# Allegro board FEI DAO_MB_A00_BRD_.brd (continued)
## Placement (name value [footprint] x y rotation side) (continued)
T56  -  [TPC12]  166.92 22.3 0 top
T57  -  [TPC12]  164.44 25.07 0 top
T58  -  [TPC12]  169.8 23.26 0 top
T59  -  [TPC12]  168.01 18.92 0 top
T60  -  [TPC12]  168.28 20.29 0 top
T61  -  [TPC12]  167.63 23.99 0 top
T62  -  [TPC12]  167.62 26.98 0 top
T63  -  [TPC12]  154.54 24.46 0 top
T104  -  [TPC12]  164.25 23.1 0 top
T107  -  [TPC12]  131.98 68.78 180 bottom
T108  -  [TPC12]  132.64 70.19 180 bottom
T109  -  [TPC12]  131.09 70.22 180 bottom
T110  -  [TPC12]  126.5 56.96 0 top
T117  -  [TPC12]  270.99 69.87 0 top
T118  -  [TPC12]  130.97 32.53 180 bottom
T119  -  [TPC12]  134.64 68.81 180 bottom
T120  -  [TPC12]  133.28 68.79 180 bottom
T121  -  [TPC12]  129.82 30.9 180 bottom
T122  -  [TPC12]  109.85 69.07 180 bottom
T123  -  [TPC12]  103.28 36.74 180 bottom
T124  -  [TPC12]  103.28 34.62 180 bottom
T125  -  [TPC12]  260.05 85 0 top
T126  -  [TPC12]  259.19 89.44 0 top
T127  -  [TPC12]  130.7 68.79 180 bottom
T128  -  [TPC12]  129.7 59.55 0 top
T130  -  [TPC12]  270.24 83.14 0 top
T131  -  [TPC12]  271.3 81.32 0 top
T132  -  [TPC12]  105.5 66.51 180 bottom
T133  -  [TPC12]  265.14 82.15 0 top
T139  -  [TPC12]  259.97 65.78 0 top
T140  -  [TPC12]  262.06 87.4 0 top
T141  -  [TPC12]  261.42 64.13 0 top
T142  -  [TPC12]  285.64 88.64 0 top
T143  -  [TPC12]  283.23 88.61 0 top
T144  -  [TPC12]  10.6 69.97 0 top
T145  -  [TPC12]  252.9 72.55 0 top
T148  -  [TPC12]  257.26 75.96 0 top
T151  -  [TPC12]  263.02 64.7 0 top
T154  -  [TPC12]  257.31 74.58 0 top
T155  -  [TPC12]  255.68 69.56 0 top
T156  -  [TPC12]  257.04 69.59 0 top
T157  -  [TPC12]  260.41 86.75 0 top
T158  -  [TPC12]  262.04 85.24 0 top
T159  -  [TPC12]  276.22 80.87 0 top
T160  -  [TPC12]  273.06 81.29 0 top
T161  -  [TPC12]  274.88 82.13 0 top
T162  -  [TPC12]  272.17 75.68 0 top
T163  -  [TPC12]  269.19 85.07 0 top
T164  -  [TPC12]  271.18 84.91 0 top
T165  -  [TPC12]  289.68 65.11 0 top
T167  -  [TPC12]  284.38 70.89 0 top
T168  -  [TPC12]  283.32 72.3 0 top
T169  -  [TPC12]  295.1 64.82 0 top
T170  -  [TPC12]  278.02 67.28 0 top
T171  -  [TPC12]  296.59 49.49 0 top
T172  -  [TPC12]  294.85 50.61 0 top
T173  -  [TPC12]  272.79 64.37 0 top
T174  -  [TPC12]  272.7 62.38 0 top
T175  -  [TPC12]  274.03 60.73 0 top
T176  -  [TPC12]  288.51 51.2 0 top
T177  -  [TPC12]  293.52 51.15 0 top
T178  -  [TPC12]  276.57 57.55 0 top
T183  -  [TPC12]  289.46 51.6 0 top
T184  -  [TPC12]  34.4 32.22 0 top
T185  -  [TPC12]  296.92 64.16 0 top
T186  -  [TPC12]  25.58 41.88 0 top
TR1  -  [TAIMA_IH-115-F_24P]  304.36 72.2 90 bottom
U1  -  [IVY-BRIDGE_BGA_1023P]  131.79 36.09 90 bottom
U2  -  [SLG55584AVTR_TDFN8_2X2]  306.49 62.79 270 bottom
U4  -  [RT9818A-44GU3_SC70-3]  189.4 31.08 180 bottom
U7  -  [TC7SH08FU_SSOP5]  187.25 28.01 270 bottom
U9  -  [EMC4021-1-EZK-TR_QFN32_5X5]  157.69 105.47 0 bottom
U15  -  [TC7SH08FU_SSOP5]  292.12 88.21 270 top
U31  -  [82579_QFN48_6X6]  284.71 78.55 0 top
U37  -  [SSX44-B-D-T1_TSSOP28]  260.11 46.98 90 bottom
U38  -  [OZ600FJ0LN_QFN32_5X5]  278.38 15.6 270 top
U39  -  [AT97SC3204-X2A14-AB_TSSOP28]  260.9 46.98 90 bottom
U40  -  [SRV05-4PTCT_SOT23-6]  288.25 29.27 90 bottom
U44  -  [PS8513BTQFN20GTR-A0_TQFN20_4X4]  238.55 75.18 0 top
U46  -  [ECE5048-LZY_DQFN132_11X11]  260.34 69.86 0 top
U48  -  [G547I2P81U_MSOP8]  18.72 43.19 0 top
U50  -  [TC7SH08FU_SSOP5]  138.41 21.93 180 bottom
U51  -  [MEC5055-LZY_DQFN132_11X11]  293.46 54.6 90 top
U52  -  [W25Q64CVSSIG_SO8]  211.78 28.82 180 bottom
U53  -  [W25Q32BVSSIG_SO8]  208 23.13 0 bottom
U58  -  [TC7SH08FU_SSOP5]  258.68 88.29 180 top
U72  -  [92HD90B2X5NLGXZBX8_QFN48_7X7]  34.86 34.66 90 top
U73  -  [74AHCT1G125GW_SOT353-5]  19.13 78.65 270 top
U74  -  [74AHCT1G125GW_SOT353-5]  16.42 77.35 90 top
U75  -  [TPS2560DRCR-PG1P1_SON10_3X3]  306.56 50.88 90 bottom
U76  -  [AP2330W-7_SC59-3]  81.9 95.86 90 bottom
U77  -  [AP2330W-7_SC59-3]  10.08 61.85 180 bottom
UC1  -  [SN74LVC1G07DCKR_SC70-5]  137.21 71.32 90 bottom
UC2  -  [74AHC1G09GW_TSSOP5]  105.72 83.61 0 bottom
UH3  -  [TC7SH08FU_SSOP5]  181.33 18.09 0 bottom
UH4  -  [BD82PPSM-QNHN-A0_BGA_989P]  170.53 18.65 270 bottom
UH5  -  [TC7SH08FU_SSOP5]  180.46 11.25 270 bottom
Y3  -  [Y_X3G025000DI1H-H_4P]  295.51 76.23 90 top
Y6  -  [Y_Q13FC1350000_2P]  290.21 47.75 0 top
YH1  -  [Y_Q13FC1350000_2P]  178.95 29.19 270 bottom
YH2  -  [Y_Q22FA2380049900_4P]  161.48 50.44 0 bottom

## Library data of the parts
C36-C39 C1169 = C_0603NEW: room: LOM
C44 C45 C550-C554 CE3 CE4 = C_0402NEW: room: TPM
C219 = C_0805NEW: room: FAN
C243 C292 C293 C297-C299 C301 C302 R159 = C_0402NEW: room: LVDS
C246 C296 C300 = C_0603NEW: room: LVDS
C266 C270-C274 C277 C278 C282 C723 C725-C729 C731 C732 C739 C1179 = C_0402NEW: room: THERMAL
C288 C289 C756 C758 PC5 PC76 PC77 PC83 PC86 PC90 PC91 PC100 PC102 PC104 PC105 PC108 PC109 PC112 PC113 PC116 PC255 PC275 PC277-PC279 PC281 PC282 PC301 PC304 PC305 PC401 PC402 PC404 PC405 PC407 PC408 PC501 PC502 PC504 PC506 PC508 PC510 PC742 PC744 PC750 PC1304 PC1312 PC1318 PC1334 PC1338 PC1339 = C_0402NEW: room: ETY-ROOM
C337 C346-C353 C1216-C1223 = C_0402NEW: room: HDMI
C338 = C_0805NEW: room: HDMI
C412 C413 C654 C675 C715 C1231 C1234 C1235 C1242-C1244 = C_0402NEW: room: USB
C458-C461 C463 C466-C471 C476-C478 = C_0402NEW: room: LAN
C462 C464 C475 = C_0603NEW: room: LAN
C559 C562 C563 C565 C567-C569 C571 C573-C576 C579 CE757 = C_0402NEW: room: OZ600
C560 C561 C564 C566 C572 C577 C578 = C_0603NEW: room: OZ600
C593 C594 C597 C599 C610-C612 C614 C644 = C_0402NEW: room: WWAN
C595 C596 C598 C600-C607 C632 = C_0402NEW: room: WLAN
C608 = C_0603NEW: room: WLAN
C609 C661-C666 C763 C765 C767 C774-C777 C779-C787 C967 C981-C983 C1246-C1249 C1278 C1279 C1316-C1333 CH53 CH111 CH112 PC78 PC1211-PC1217 = C_0402NEW
C613 = C_0805NEW: room: WWAN
C615 = C_D2E: room: WWAN
C616 C628-C631 = C_0402NEW: room: SIM
C617 C618 C1309 C1310 CH2-CH5 CH18 CH19 CH31-CH35 CH43 CH45-CH52 CH54-CH56 CH59 CH60 CH63 CH66-CH69 CH72 CH74-CH79 CH81 CH82 CH84 CH86-CH93 CH96-CH98 CH101-CH104 CH107 CH109 CH110 = C_0402NEW: room: PCH
C619-C625 C627 C650 = C_0402NEW: room: WPAN
C626 = C_0603NEW: room: WPAN
C651 C1245 = C_B2: room: USB
C676 C1230 = C_0805NEW: room: USB
C705 C714 = C_0603NEW: room: SIO
C706-C710 C712 C713 C716 = C_0402NEW: room: SIO
C720-C722 C735 C737 C741-C744 C747 = C_0402NEW: room: KBC
C730 = C_0603NEW: room: THERMAL
C740 = C_0603NEW: room: KBC
C745 C746 = C_0402NEW: room: FLASH ROM
C749-C752 C755 C759 = C_0402NEW: room: TOUCH.PAD
C760 C768 C769 C772 = C_0603NEW: room: +3.3V_LAN SOURCE
C761 = C_0805NEW: room: +5V_RUN_SOURCE
C762 = C_0402NEW: room: +3.3V_ALW_PCH SOURCE
C764 = C_0805NEW: room: +3.3V_RUN_SOURCE
C766 = C_0402NEW: room: +3.3V_RUN_SOURCE
C770 = C_0402NEW: room: +3.3VM SOURCE
C771 = C_0402NEW: room: +1.5V_RUN_SOURCE
C773 = C_0402NEW: room: +1.05VRUN_SOURCE
C778 = C_0402NEW: room: LVDS SW
C952 C954-C956 C958 C960 C962-C966 C1163 C1180 = C_0603NEW: room: CODEC
C953 C957 C959 C961 C973-C980 C994 C1105 C1106 = C_0402NEW: room: CODEC
C1104 = C_1808: room: LOM
C1167 C1168 = C_0402NEW: room: LOM
C1177 C1178 = C_0805NEW: room: LAN
C1201-C1210 C1224 C1225 = C_0402NEW: room: CRT
C1211-C1213 = C_0402NEW: room: AJACK
C1232 = C_B2: room: ESATA
C1233 C1236-C1239 = C_0402NEW: room: ESATA
C1304 = C_0402NEW: room: FP
C1305-C1307 = C_0402NEW: room: BT
C1308 = C_0402NEW: room: LID
C1311 = C_0402NEW: room: CAM
CC65 = C_0402NEW: room: XDP1
CC135 = C_0603NEW: room: +1.5V_CPU_VDDQ SOURCE
CC136 = C_0402NEW: room: +1.5V_CPU_VDDQ SOURCE
CC140 CC141 CC149 CC150 CC156 CC174 CC175 CC177-CC179 CC250-CC264 CC573 CC574 PC1137-PC1142 PC1147-PC1151 PC1172 PC1175-PC1186 PC1188-PC1210 = C_0402NEW: room: CPU
CC161-CC166 CC168-CC171 CC180 CC181 CC183 = C_0603NEW: room: CPU
CC167 PC1157 = C_D3: room: CPU
CC172 CC176 PC1158 = C_D2: room: CPU
CD1-CD8 CD17-CD30 CD39-CD44 = C_0402NEW: room: MEMORY
CD9-CD15 CD31-CD37 = C_0603NEW: room: MEMORY
CD16 CD38 = C_D3: room: MEMORY
CH1 CH6 = C_0402NEW: room: XDP2
CH30 CH44 CH70 CH71 CH73 CH85 CH106 = C_0603NEW: room: PCH
CH36 CH64 CH65 CH105 = C_0805NEW: room: PCH
CH94 CH95 = C_B2: room: PCH
CMOS1 ME1 = SHORTPADS: User Part Number: PART#; room: PCH
D2 D31 = RB751S40T1_SOD523-2: room: ETY-ROOM
D6 = BAT54CW_SOT323-3: room: LVDS
D9 D73 = PESD5V0U2BT_SOT23-3
D23 PD7 = PESD24VS2UT_SOT23-3
D37 = PESD5V0U2BT_SOT23-3: room: TOUCH.PAD
D59 D62 D65-D69 DH2 DH3 = RB751V40_SC76-2: room: ETY-ROOM
D72 D77 D83 D90 = PESD5V0U2BT_SOT23-3: room: USB
D78 = IP4292CZ10-TB_XSON10U10: room: ETY-ROOM
D81 D82 = AZ5125-02SPR7G_SOT23-3: room: ETY-ROOM
D87 = PESD5V0U2BT_SOT23-3: room: ESATA
D88 = IP4292CZ10-TB_XSON10U10: room: ESATA
D89 = IP4292CZ10-TB_XSON10U10: room: USB
D91-D94 = RB751S40T1_SOD523-2
DE1 DE2 = AZ5125-02SPR7G_SOT23-3: room: CAM
FD1-FD4 = FIDUCIAL_C40M80
H1-H3 H5 H7 H9 H10 = H_2P8
H4 H6 H8 H26 = H_2P3
H11 = H_5P4N
H12 = H_2P0
H13 H14 H16 H17 = H_3P2
H19-H22 = H_3P8
H23 = H_2P8X2P3
H24 = H_2P5X2P0
JBT1 = ACES_50224-0120N-001_12P: room: BT
JCAP2 JLED1 = ACES_50506-00841-P01_8P-T
JCRT1 = TYCO_2041127-1_15P: room: ETY-ROOM
JDEG2 = HB_A531015-SCHR21_10P: room: KBC
JDIMM1 = TYCO_2-2013022-1_204P: room: ETY-ROOM
JDIMM2 = TYCO_2-2013287-1_204P: room: ETY-ROOM
JESA1 = TAIWI_EU147-167CRL-TWD_16P: room: ESATA
JFAN1 = ACES_50271-0040N-001_4P: room: ETY-ROOM
JFP1 = ACES_50505-00641-001_6P-T: room: ETY-ROOM
JHDMI1 = HONGL_13-13201904CP_19P: room: HDMI
JHP1 = SINGA_2SJ3053-100111F_6P-T: room: ETY-ROOM
JLID1 = HB_A080415-SAHR21_4P-T: room: ETY-ROOM
JLOM1 = SANTA_130456-241_13P-T
JLVDS1 = STARC_107K40-000001-G2_40P: room: ETY-ROOM
JLVDS2 = E-T_3703K-F12N-03R_12P
JMINI1 = LCN_DAN08-52406-0500_52P: room: WWAN
JMINI2 JMINI3 = LCN_DAN08-52406-0500_52P: room: ETY-ROOM
JRTC1 = ACES_50271-0020N-001_2P: room: ETY-ROOM
JSC1 = HB_A081015-SAHR21_10P-T: room: ETY-ROOM
JSD1 = T-SOL_156-4000000606_15P-T: room: ETY-ROOM
JSIM1 = HB_5620821-SICR11_9P: room: ETY-ROOM
JSNIF1 = ACES_50504-0040N-001_4P: room: IO
JSPK1 = ACES_50269-00401-001_4P-T: room: ETY-ROOM
JTAA1 = ACES_50169-01441-001_14P-T: room: ETY-ROOM
JTAG1 = SHORTPADS: User Part Number: PART#; room: KBC
JTP1 = ACES_50506-01641-P01_16P-T: room: TOUCH.PAD
JUSB1 = SANTA_373070-1_9P-T: room: ETY-ROOM
JUSB3 = SANTA_373070-1_9P-T: room: USB
JXDP1 = MOLEX_52435-2671_26P-T: room: ETY-ROOM
JXDP2 = MOLEX_52435-2671_26P-T: room: PCH
L10 = MURAT_DLW21SN121SQ2L_4P: room: LVDS
L19-L22 = MURAT_DLW21SN900HQ2L_0805_4P-S: room: HDMI
L29 = TAIYO_CBC2012T4R7M_2P: room: LAN
L44 L47 = MURAT_BLM18BD601SN1D_2P: room: OZ600
L45 = MURAT_BLM18PG471SN1D_2P: room: OZ600
L51 L113 = MURAT_DLW21SN900SQ2L_0805_4P: room: USB
L52 = MURAT_DLW21SN900SQ2L_0805_4P-S
L54 L55 = MURAT_BLM15AG601SN1D_2P: room: TOUCH.PAD
L77 = MURAT_BLM21PG600SN1D_L0805_2P: room: CODEC
L91-L94 = MURAT_BLM18PG121SN1D_2P: room: CODEC
L95 L96 L114 L115 = MURAT_DLW21SN900HQ2L_0805_4P: room: USB
L99-L103 = MURAT_BLM15AG121SN1D_2P: room: CRT
L104-L106 = MURAT_BLM18BD601SN1D_2P: room: AJACK
L110 L112 = MURAT_DLW21SN900HQ2L_0805_4P: room: ESATA
L111 = MURAT_DLW21SN900SQ2L_0805_4P: room: ESATA
L116-L123 = DELTA_0402HS-9N0EJTS_2P
L124-L131 = DELTA_0603CS-120EJTS_2P
LE3 = MURAT_BLM15BB221SN1D_2P: room: CODEC
LE92 = MURAT_BLM15BB221SN1D_2P: room: LVDS
LH1 = TDK_GLFR1608T1R0M-LR_2P: room: PCH
LH6 LH7 = TAIYO_LBR2012T100M_2P: room: PCH
LH8 = TDK_MLG1608BR10JT_2P: room: PCH
PBATT1 = SUYIN_200277MR009F515ZR_7P: room: ETY-ROOM
PC3 PC101 PC107 PC115 PC117 PC253 PC263 PC272 PC280 PC505 PC714 PC715 PC1309 PC1311 PC1327 = C_0603NEW: room: ETY-ROOM
PC4 PC11-PC14 PC16 PC18 = C_0402NEW: room: P_DCIN
PC8 PC17 = C_0402NEW: room: VSB
PC9 = C_0603NEW: room: VSB
PC10 = C_0805NEW: room: P_DCIN
PC15 PC103 PC106 PC118 PC119 PC733 PC734 PC746 PC747 PC1314 PC1315 PC1330-PC1332 = C_0805NEW: room: CPU_CORE
PC74 PC75 = C_0603NEW: room: 0.8V_VCC
PC80 PC87 PC92 = C_0402NEW: room: 0.8V_VCC
PC81 PC82 PC84 PC85 = C_0805NEW: room: 1P8V
PC88 PC89 PC114 PC274 PC276 PC300 PC302 PC303 PC400 PC403 PC500 PC503 = C_0805NEW: room: ETY-ROOM
PC110 PC111 PC265 PC406 PC511 = C_B2: room: ETY-ROOM
PC120 PC121 PC215 PC702-PC711 PC722 PC723 PC727 PC736-PC741 PC743 PC745 PC749 PC751 PC752 PC754 = C_0402NEW: room: CPU_CORE
PC306 PC307 = C_0402NEW: room: P_1P8V
PC701 PC719 PC729 = C_0402NEW: room: DDR_VTT
PC732 = C_B2
PC748 = C_0805NEW
PC753 = C_D
PC1111-PC1136 PC1154-PC1156 PC1159-PC1162 PC1167 = C_0805NEW: room: CPU
PC1165 PC1166 PC1168-PC1170 = C_SX: room: CPU
PC1301-PC1303 PC1305 PC1307 PC1310 PC1313 PC1316 PC1317 PC1319-PC1321 PC1323-PC1326 PC1328 PC1329 PC1333 PC1335-PC1337 PC1340 PC1341 = C_0402NEW: room: CHARGER
PC1306 = C_0603NEW: room: CHARGER
PC1322 = C_0402NEW: room: ADP3209
PC1342 = C_0402NEW: room: P_SELECTOR
PD4 = BAS40CW_SOT323-3: room: ETY-ROOM
PD5 PD6 = PESD24VS2UT_SOT23-3: room: SWITCH
PD100 = LL34: room: ETY-ROOM
PD1301 = RB751V-40_SOD323-2: room: ETY-ROOM
PH700 PH703 PR500 PR702-PR705 PR707-PR712 PR715 PR722 PR725 PR727 PR728 PR730 PR735-PR737 PR740-PR742 PR746 PR747 PR750 PR754 PR757 PR759 = R_0402NEW: room: CPU_CORE
PH701 PH702 PR79 PR82 PR87 PR89 PR101-PR106 PR111 PR114 PR115 PR201 PR205 PR206 PR237 PR238 PR300 PR302-PR305 PR307 PR408 PR409 PR701 PR744 PR1313 PR1317 PR1323 PR1324 PR1333 PR1335 PR1336 PR1346 PR1347 PR1351 R778 R1610 R1611 R1622 R1623 R1663 R1668 R1670 = R_0402NEW: room: ETY-ROOM
PJP3 = JUMP_43X79
PJP19 PJP200 PJP300 PJP301 PJP400 PJP401 PJP500-PJP502 = JUMP_43X79: room: DDR_VTT_0.75V
PJP20 = JUMP_43X118: room: 0.8V_VCC
PJP21 PJP62 = JUMP_43X39: room: 0.8V_VCC
PJP60 PJP61 = JUMP_43X39
PJP101 PJP103 PJP201 = JUMP_43X118: room: ETY-ROOM
PJP203 PJP204 PJP702 = JUMP_43X39: room: VGA_CORE
PJP801 = JUMP_43X39: room: CHARGER
PJPDC1 = ACES_50299-00501-003_5P: room: ETY-ROOM
PL2 PL5 = TAIYO_FBMJ4516HS720NT_2P: room: P_DCIN
PL4 = MURAT_BLM18BD102SN1D_L0603_2P: room: P_DCIN
PL6 = TAIYO_FBMJ4516HS720NT_2P
PL15 PL200 PL400 PL500 = TAI-T_VMPI0703AR-1R0M-Z01_2P: room: VDDCI
PL100 PL700 = TAI-T_HCB2012KF-121T50_2P: room: ETY-ROOM
PL101 PL103 PL1301 = TOKO_FDSD0630-H-4R7M-P3_2P: room: ETY-ROOM
PL301 PL1300 = TAIYO_NRS4018T1R0NDGJ_2P: room: ETY-ROOM
PL702 PL704 = CYNTE_PDME064T-R36MS1R405_4P: room: ETY-ROOM
PQ2 = FDV301N_NL_SOT23-3: room: P_DCIN
PQ3 = MMST3904-7-F_SOT323-3: room: P_DCIN
PQ4 = TP0610K-T1-E3_SOT23-3: room: VSB
PQ5 = FDS6679AZ_SO8: room: P_DCIN
PQ6 = L2N7002WT1G_SC70-3: room: VSB
PQ100-PQ103 PQ200 PQ210 PQ400 PQ405 PQ500 PQ501 = SI7326DN-T1-E3_PAK1212-8: room: ETY-ROOM
PQ104 PQ1307 PQ1311 = 2N7002DW-T-R7_SOT363-6: room: P_SELECTOR
PQ105 = DTC115EUA_SC70-3: room: ETY-ROOM
PQ704 PQ708 = MDU1516URH_POWERDFN56-8-5: room: ETY-ROOM
PQ706 PQ710 PQ711 = SI7170DP-T1-GE3_POWERPAK8-5: room: CPU_CORE
PQ1300 = SI7121DN-T1-GE3_POWERPAK8-5: room: ETY-ROOM
PQ1301 = FDS6679AZ_SO8
PQ1304 PQ1305 = SI7716ADN-T1-GE3_POWERPAK8-5: room: ETY-ROOM
PQ1306 = 2N7002DW-T-R7_SOT363-6: room: ETY-ROOM
PR1 PR6-PR9 PR11-PR17 PR21-PR23 = R_0402NEW: room: P_DCIN
PR19 PR20 PR112 = R_0402NEW: room: VSB
PR24 = R_0805NEW: room: P_DCIN
PR25 = R0402_0OHM-NEW: room: VSB
PR80 PR83 PR88 PR90 PR91 = R0402_0OHM-NEW: room: 0.8V_VCC
PR84 = R_0603NEW: room: 0.8V_VCC
PR85 = R_1206NEW: room: 0.8V_VCC
PR86 = R_0402NEW: room: 0.8V_VCC
PR100 PR116 PR232 PR236 PR306 PR403 PR503 PR1342 R1624 = R0402_0OHM-NEW: room: ETY-ROOM
PR107 PR108 PR200 PR401 PR502 PR717 PR720 PR749 PR755 PR758 PR763 = R_0603NEW: room: CPU_CORE
PR109 PR110 PR203 PR404 PR504 PR1332 = R_1206NEW: room: ETY-ROOM
PR113 = R_0402NEW: room: P_3V_5V
PR202 PR1322 = R_0603NEW: room: ETY-ROOM
PR204 PR400 PR402 PR405-PR407 PR501 PR505 PR507 PR510 = R_0402NEW: room: 1P5V
PR301 = R_0603NEW: room: P_1P8V
PR410 PR724 PR729 R589-R592 R743 R745-R747 R750 R752 R755 R808 R813 R874 R877 R881 R888 R928 R938 R950 R1090 R1594 R1595 R1618 R1621 R1627 R1629 R1630 R1661 R1718-R1744 RC80 RC81 RC134 RH101 RH103 RH145 RH165 RH166 RH202 RH269 RH365 = R_0402NEW
PR508 PR513 = R0402_0OHM-NEW: room: 1P05V
PR514 = R_0402NEW: room: 1P05V
PR713 PR714 PR716 PR718 PR719 PR721 PR723 PR726 PR732 = R0402_0OHM-NEW: room: CPU_CORE
PR751 PR760 = R_1206NEW: room: CPU_CORE
PR1301 PR1326 = R_1206_4P-D: room: ETY-ROOM
PR1303-PR1308 PR1310 PR1311 PR1316 PR1325 PR1327-PR1330 PR1334 PR1338 PR1340 PR1341 PR1343 PR1348-PR1350 = R_0402NEW: room: CHARGER
PR1318 PR1319 = R_0603NEW: room: CHARGER
PR1320 PR1331 PR1339 = R0402_0OHM-NEW: room: CHARGER
PU7 = TPS51461RGER_QFN24_4X4: room: ETY-ROOM
PU100 = RT8205EGQW_WQFN24_4X4: room: ETY-ROOM
PU200 = RT8207MZQW_WQFN20_3X3: room: ETY-ROOM
PU300 = SY8033BDBC_DFN10_3X3: room: ETY-ROOM
PU400 PU500 = TPS51218DSCR_SON10_3X3: room: ETY-ROOM
PU700 = ISL95835HRTZ-T_TQFN40_5X5: room: CPU_CORE
PU1300 = BQ24745RHDR_QFN28_5X5: room: ETY-ROOM
PU1302 = 74AHC1G08GW_SOT353-5: room: PCH
PU1304 = LM393DR_SO8: room: ETY-ROOM
PWRSW1 = SHORTPADS: User Part Number: PART#; room: TOUCH.PAD
Q12-Q14 = MMBT3904WT1G_SC70-3: room: THERMAL
Q16 = PMST3904_SOT323-3: room: THERMAL
Q18 Q49 Q58 = SI3456DDV-T1-GE3_TSOP6: room: ETY-ROOM
Q19 = DMN66D0LDW-7_SOT363-6: room: LVDS
Q20 = PDTC124EU_SC70-3: room: LVDS
Q21 = FDC654P-G_SSOT-6: room: ETY-ROOM
Q22 = SSM3K7002FU_SC70-3: room: LVDS
Q23 = PMV65XP_SOT23-3: room: LVDS
Q26 Q121 = SSM3K7002FU_SC70-3: room: HDMI
Q34 = SI3456DDV-T1-GE3_TSOP6: room: LAN
Q35 = DMN66D0LDW-7_SOT363-6: room: LAN
Q38 = SI3456DDV-T1-GE3_TSOP6: room: WLAN
Q39 Q124 = DMN66D0LDW-7_SOT363-6: room: WLAN
Q40 = SI3456DDV-T1-GE3_TSOP6: room: WWAN
Q41 = DMN66D0LDW-7_SOT363-6: room: WWAN
Q42 = SI3456DDV-T1-GE3_TSOP6: room: WPAN
Q43 = DMN66D0LDW-7_SOT363-6: room: WPAN
Q45 Q47 Q50 = SSM3K7002FU_SC70-3: room: KBC
Q48 = SSM3K7002FU_SC70-3: room: USB
Q51 = DMN66D0LDW-7_SOT363-6: room: +3.3V_ALW_PCH SOURCE
Q52 = DMN66D0LDW-7_SOT363-6: room: +5VRUN SOURCE
Q53 Q66 Q126 = SSM3K7002FU_SC70-3
Q55 Q61 = DMN3030LSS-13_SOP8L-8: room: +5V_RUN_SOURCE
Q56 = SSM3K7002FU_SC70-3: room: +3.3V_RUN_SOURCE
Q57 = DMN66D0LDW-7_SOT363-6: room: +3.3VM SOURCE
Q59 = AO4728L_SO8: room: ETY-ROOM
Q60 Q67-Q72 = SSM3K7002FU_SC70-3: room: DISCHARGE
Q62 = SSM3K7002FU_SC70-3: room: +5V_RUN_SOURCE
Q63 = SI4164DY-T1-GE3_SO8: room: +1.05VRUN_SOURCE
Q64 = SSM3K7002FU_SC70-3: room: +1.05VRUN_SOURCE
Q73 Q77 = SSM3K7002FU_SC70-3: room: WWAN
Q74 Q78 Q80 Q83 Q84 = DMN66D0LDW-7_SOT363-6: room: LED
Q75 Q79 Q81 = PDTA114EU_SC70-3: room: LED
Q107 = DMN66D0LDW-7_SOT363-6: room: CODEC
Q120 = DMN66D0LDW-7_SOT363-6: room: HDMI
Q127 = PDTC124EU_SC70-3
QC1 = SSM3K7002FU_SC70-3: room: CPU
QC2 = BSS138W-7-F_SOT323-3: room: CPU
QC3 = AO4728L_SO8: room: +1.5V_CPU_VDDQ SOURCE
QC4 = DMN66D0LDW-7_SOT363-6: room: +1.5V_CPU_VDDQ SOURCE
QC5 = NTR4503NT1G_SOT23-3
QD1 QD2 = BSS138-G_SOT23-3: room: ETY-ROOM
QH4 QH7 QH8 = SSM3K7002FU_SC70-3: room: PCH
QH5 QH6 = DMN66D0LDW-7_SOT363-6: room: PCH
R3 R457 R760 R761 R763 R766 R767 R769 R772 R774-R777 R780 R782 R786 R789-R791 R793-R796 R798 R800 R802-R805 R807 R878 = R_0402NEW: room: SIO
R160 R412-R414 R422 R423 R1137 R1138 R1632 = R_0402NEW: room: LVDS
R385 R387-R391 R393 R395 R399 R402-R404 R406 R426 = R_0402NEW: room: THERMAL
R418 R420 R759 R764 R768 R771 R773 R785 R799 R810-R812 R814 R817 R818 R820-R824 R827-R829 R835 R836 R838 R841 R843 R845-R852 R854 R856 R858-R861 R863 R864 R869-R872 R875 R876 R879 R880 R882-R887 R889 R893 R941 R942 R1118 R1125 R1156 R1169 R1171 R1179 R1197 R1658 R1659 = R_0402NEW: room: KBC
R427 R428 = R_0402NEW-S: room: LVDS
R448-R450 R452-R456 R458 R1128 R1152 R1153 R1165 R1168 = R_0402NEW: room: HDMI
R545-R547 R549 R553 R554 R557 R561 R562 R564 R565 = R_0402NEW: room: LAN
R548 = R_0805NEW
R551 R552 R555 R1144 R1187 = R0402_0OHM-NEW: room: LAN
R563 = R_1206NEW
R656-R660 RE5 RE6 = R_0402NEW: room: TPM
R663-R665 R668-R670 R672-R674 R676 R677 R826 RE678 = R_0402NEW: room: OZ600
R692 R693 R698 R699 R701 R705 R706 R713-R716 R718 R1620 = R_0402NEW: room: WLAN
R694 R695 R697 R719 R721-R723 R725 R726 R1157-R1160 R1625 = R_0402NEW: room: WWAN
R700 R702 R703 R707 = R0402_0OHM-NEW: room: WLAN
R704 = R0402_0OHM-NEW: room: WWAN
R708 R711 R712 R728-R730 R733 R1628 = R_0402NEW: room: WPAN
R735 = R0402_0OHM-NEW: room: EXPRESS
R736 R740 R1603-R1606 R1702-R1707 = R_0402NEW-S: room: USB
R737 R741 R742 R749 R751 R806 R1717 RH336 RH338 = R0402_0OHM-NEW
R738 R765 R797 = R0402_0OHM-NEW: room: SIO
R744 = R_0402NEW: room: EXPRESS
R784 R1626 = R0402_0OHM-NEW: room: USB
R815 R853 R855 R862 R867 R1068 R1180 = R0402_0OHM-NEW: room: KBC
R816 R1613 R1614 R1677 = R_0402NEW: room: USB
R873 = R0402_0OHM-NEW: room: TPM
R890 R891 R894-R901 R906 R912 = R_0402NEW: room: FLASH ROM
R892 RH2 RH11 RH22 RH23 RH25-RH31 RH35 RH38 RH40-RH50 RH52 RH53 RH59 RH66 RH74-RH81 RH87 RH91 RH94 RH97-RH100 RH102 RH105 RH111 RH112 RH114 RH118 RH123 RH124 RH126 RH127 RH131-RH134 RH137 RH139 RH140 RH142 RH144 RH149 RH151 RH152 RH158 RH160 RH163 RH164 RH170-RH174 RH177 RH178 RH181 RH183 RH203 RH208 RH213 RH256 RH260 RH262 RH263 RH266-RH268 RH270 RH271 RH273 RH278 RH279 RH287 RH298-RH306 RH311 RH313-RH317 RH321 RH324-RH333 RH341-RH352 RH354 RH355 RH357 RH358 RH363 RH364 = R_0402NEW: room: PCH
R902 R903 = R_0402NEW: room: TOUCH.PAD
R905 R907 R908 R1619 = R_0402NEW: room: +3.3V_ALW_PCH SOURCE
R909 = R_0402NEW: room: +5VRUN SOURCE
R910 R933 = R_0402NEW: room: +5V_RUN_SOURCE
R913 R940 = R_0402NEW: room: +3.3V_RUN_SOURCE
R916 R927 R929 = R_0603NEW: room: DISCHARGE
R917-R919 R1617 = R_0402NEW: room: +3.3VM SOURCE
R920 R921 = R_0402NEW: room: +1.5V_RUN_SOURCE
R923-R926 = R_0402NEW: room: DISCHARGE
R930 R931 = R_0402NEW: room: +1.05VRUN_SOURCE
R932 R937 R949 R951 R955 R958 R959 = R_0402NEW: room: LED
R935 R936 = R0402_0OHM-NEW: room: FLASH ROM
R1076-R1078 R1081-R1083 R1086 R1087 R1096 R1099 R1119 R1120 R1141-R1143 R1650 R1651 R1660 = R_0402NEW: room: CODEC
R1089 R1091 R1111-R1114 = R_0402NEW: room: LOM
R1095 = R0805_0OHM-NEW: room: CODEC
R1161 = R0603_0OHM-NEW: room: TOUCH.PAD
R1162 = R_0603NEW: room: TOUCH.PAD
R1163 = R0402_0OHM-NEW: room: HDMI
R1638 = R_0402NEW: room: +3.3V_LAN SOURCE
R1641-R1647 R1669 = R_0402NEW: room: CRT
R1652 R1662 = R0402_0OHM-NEW: room: CODEC
R1678-R1683 = R_0402NEW-S: room: ESATA
R1708-R1710 = R_0402NEW: room: BT
RC1 RC2 RC4 RC8 RC10 RC12 RC16-RC19 RC25 RC27-RC29 RC32 RC35 RC40-RC45 RC47 RC48 RC50-RC54 RC56 RC57 RC60 RC61 RC63 RC64 RC66 RC69-RC71 RC75 RC76 RC78 RC84 RC96-RC100 RC120-RC123 RC126 RC128 RC130 RC133 RC140 RC141 = R_0402NEW: room: CPU
RC5 RC7 RC9 RC124 RH108 RH109 = R_0402NEW: room: XDP1
RC6 RH106 RH107 = R0402_0OHM-NEW: room: XDP1
RC23 RC24 RC26 RC46 RC67 RC68 RC129 = R0402_0OHM-NEW: room: CPU
RC72-RC74 RC82 RC143 = R_0402NEW: room: +1.5V_CPU_VDDQ SOURCE
RC79 = R0402_0OHM-NEW: room: +1.5V_CPU_VDDQ SOURCE
RD1 RD2 RD7 RD10-RD12 = R0402_0OHM-NEW: room: MEMORY
RD3-RD6 RD8 RD9 RD13 RD14 = R_0402NEW: room: MEMORY
RH21 RH24 RH283 RH284 = R_0402NEW: room: XDP2
RH113 RH150 RH201 RH286 RH290 RH309 RH323 RH359 RH360 = R0402_0OHM-NEW: room: PCH
RH197 RH215 = R0603_0OHM-NEW: room: PCH
RH288 = R_0603NEW: room: PCH
SW1 = SW_SKRBAAE010_4P
T56-T63 T104 T117 T144 = TPC12: room: PCH
T107-T109 T118-T124 T127 T132 = TPC12: room: CPU
T110 T125 T126 T128 T130 T131 T133 T139-T141 T145 T148 T151 T154-T165 T167-T178 T183-T186 = TPC12
T142 T143 = TPC12: room: LAN
TR1 = TAIMA_IH-115-F_24P: room: ETY-ROOM
U1 = IVY-BRIDGE_BGA_1023P: room: ETY-ROOM
U2 = SLG55584AVTR_TDFN8_2X2: room: USB
U4 = RT9818A-44GU3_SC70-3: room: KBC
U7 = TC7SH08FU_SSOP5: room: ETY-ROOM
U9 = EMC4021-1-EZK-TR_QFN32_5X5: room: ETY-ROOM
U15 = TC7SH08FU_SSOP5: room: LAN
U31 = 82579_QFN48_6X6: room: LAN
U37 = SSX44-B-D-T1_TSSOP28: room: TCM
U38 = OZ600FJ0LN_QFN32_5X5: room: OZ600
U39 = AT97SC3204-X2A14-AB_TSSOP28: room: ETY-ROOM
U40 = SRV05-4PTCT_SOT23-6
U44 = PS8513BTQFN20GTR-A0_TQFN20_4X4
U46 = ECE5048-LZY_DQFN132_11X11: room: SIO
U48 = G547I2P81U_MSOP8: room: USB
U50 = TC7SH08FU_SSOP5: room: KBC
U51 = MEC5055-LZY_DQFN132_11X11: room: KBC
U52 = W25Q64CVSSIG_SO8: room: ETY-ROOM
U53 = W25Q32BVSSIG_SO8: room: FLASH ROM
U58 = TC7SH08FU_SSOP5: room: LED
U72 = 92HD90B2X5NLGXZBX8_QFN48_7X7: room: CODEC
U73 U74 = 74AHCT1G125GW_SOT353-5: room: ETY-ROOM
U75 = TPS2560DRCR-PG1P1_SON10_3X3: room: USB
U76 U77 = AP2330W-7_SC59-3
UC1 = SN74LVC1G07DCKR_SC70-5: room: CPU
UC2 = 74AHC1G09GW_TSSOP5: room: CPU
UH3 UH5 = TC7SH08FU_SSOP5: room: PCH
UH4 = BD82PPSM-QNHN-A0_BGA_989P: room: ETY-ROOM
Y3 = Y_X3G025000DI1H-H_4P: room: ETY-ROOM
Y6 = Y_Q13FC1350000_2P: room: KBC
YH1 = Y_Q13FC1350000_2P: room: PCH
YH2 = Y_Q22FA2380049900_4P: room: ETY-ROOM

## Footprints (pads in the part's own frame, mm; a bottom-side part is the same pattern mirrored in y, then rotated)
2N7002DW-T-R7_SOT363-6
  oval 0.381x1.397 smd: 1(0,0) 2(0.65,0) 3(1.3,0) 4(1.3,1.725) 5(0.65,1.725) 6(0,1.725)
74AHC1G08GW_SOT353-5
  oval 0.381x0.813 smd: 1(0,0) 2(0.65,0) 3(1.3,0) 4(1.3,1.8) 5(0,1.8)
74AHC1G09GW_TSSOP5
  oval 0.381x1.346 smd: 1(0,0) 2(0.65,0) 3(1.3,0) 4(1.3,1.79) 5(0,1.79)
74AHCT1G125GW_SOT353-5
  oval 0.457x1.321 smd: 1(0,0) 2(0.65,0) 3(1.3,0) 4(1.3,1.8) 5(0,1.8)
92HD90B2X5NLGXZBX8_QFN48_7X7
  oval 0.254x0.991 smd: 1(0,-0.025) 2(0.5,-0.025) 3(1,-0.025) 4(1.5,-0.025) 5(2,-0.025) 6(2.5,-0.025) 7(3,-0.025) 8(3.5,-0.025) 9(4,-0.025) 10(4.5,-0.025) 11(5,-0.025) 12(5.5,-0.025) 25(5.5,6.975) 26(5,6.975) 27(4.5,6.975) 28(4,6.975) 29(3.5,6.975) 30(3,6.975) 31(2.5,6.975) 32(2,6.975) 33(1.5,6.975) 34(1,6.975) 35(0.5,6.975) 36(0,6.975)
  oval 0.991x0.254 smd: 13(6.25,0.725) 14(6.25,1.225) 15(6.25,1.725) 16(6.25,2.225) 17(6.25,2.725) 18(6.25,3.225) 19(6.25,3.725) 20(6.25,4.225) 21(6.25,4.725) 22(6.25,5.225) 23(6.25,5.725) 24(6.25,6.225) 37(-0.75,6.225) 38(-0.75,5.725) 39(-0.75,5.225) 40(-0.75,4.725) 41(-0.75,4.225) 42(-0.75,3.725) 43(-0.75,3.225) 44(-0.75,2.725) 45(-0.75,2.225) 46(-0.75,1.725) 47(-0.75,1.225) 48(-0.75,0.725)
  rect 5.639x5.639 smd: 49(2.75,3.475)
82579_QFN48_6X6
  oval 0.203x1.041 smd: 1(0,0) 2(0.4,0) 3(0.8,0) 4(1.2,0) 5(1.6,0) 6(2,0) 7(2.4,0) 8(2.8,0) 9(3.2,0) 10(3.6,0) 11(4,0) 12(4.4,0) 25(4.4,5.95) 26(4,5.95) 27(3.6,5.95) 28(3.2,5.95) 29(2.8,5.95) 30(2.4,5.95) 31(2,5.95) 32(1.6,5.95) 33(1.2,5.95) 34(0.8,5.95) 35(0.4,5.95) 36(0,5.95)
  oval 1.041x0.203 smd: 13(5.175,0.775) 14(5.175,1.175) 15(5.175,1.575) 16(5.175,1.975) 17(5.175,2.375) 18(5.175,2.775) 19(5.175,3.175) 20(5.175,3.575) 21(5.175,3.975) 22(5.175,4.375) 23(5.175,4.775) 24(5.175,5.175) 37(-0.775,5.175) 38(-0.775,4.775) 39(-0.775,4.375) 40(-0.775,3.975) 41(-0.775,3.575) 42(-0.775,3.175) 43(-0.775,2.775) 44(-0.775,2.375) 45(-0.775,1.975) 46(-0.775,1.575) 47(-0.775,1.175) 48(-0.775,0.775)
  rect 4.394x4.394 smd: 49(2.2,2.975)
ACES_50169-01441-001_14P-T
  oval 0.254x1.397 smd: 1(0,0) 2(0,-5.4) 3(-0.5,0) 4(-0.5,-5.4) 5(-1,0) 6(-1,-5.4) 7(-1.5,0) 8(-1.5,-5.4) 9(-2,0) 10(-2,-5.4) 11(-2.5,0) 12(-2.5,-5.4) 13(-3,0) 14(-3,-5.4)
ACES_50224-0120N-001_12P
  oval 0.61x1.549 smd: 1(0,0) 2(1,0) 3(2,0) 4(3,0) 5(4,0) 6(5,0) 7(6,0) 8(7,0) 9(8,0) 10(9,0) 11(10,0) 12(11,0)
  rect 1.194x1.803 smd: 13(-1.3,-3.875) 14(12.3,-3.875)
ACES_50269-00401-001_4P-T
  oval 0.61x1.245 smd: 1(0,0) 2(1.2,0) 3(2.4,0) 4(3.6,0)
  rect 0.711x0.787 smd: 5(-1.15,-3.975) 6(4.75,-3.975)
ACES_50271-0020N-001_2P
  oval 0.787x1.6 smd: 1(0,0) 2(1.25,0)
  rect 2.108x2.997 smd: 3(3.8,-2.9) 4(-2.55,-2.9)
ACES_50271-0040N-001_4P
  oval 0.787x1.6 smd: 1(0,0) 2(-1.25,0) 3(-2.5,0) 4(-3.75,0)
  rect 2.108x2.997 smd: 5(2.55,-2.9) 6(-6.3,-2.9)
ACES_50299-00501-003_5P
  round 1.803 hole 1.803 unplated: (-0.2,5.2) (8.2,5.2)
  oval 0.889x2.388 smd: 1(0,0) 2(2,0) 3(4,0) 4(6,0) 5(8,0)
ACES_50504-0040N-001_4P
  oval 0.61x1.295 smd: 1(0,0) 2(1,0) 3(2,0) 4(3,0)
  rect 2.159x2.21 smd: 5(-2.825,-3.05) 6(5.825,-3.05)
ACES_50505-00641-001_6P-T
  oval 0.61x1.295 smd: 1(0,0) 2(1,0) 3(2,0) 4(3,0) 5(4,0) 6(5,0)
  rect 0.991x2.007 smd: 7(-2.6,-3.25) 8(7.6,-3.25)
ACES_50506-00841-P01_8P-T
  oval 0.305x0.889 smd: 1(0,0) 2(0.5,0) 3(1,0) 4(1.5,0) 5(2,0) 6(2.5,0) 7(3,0) 8(3.5,0)
  rect 0.991x2.007 smd: 9(-2.1,-3.05) 10(5.6,-3.05)
ACES_50506-01641-P01_16P-T
  oval 0.305x0.889 smd: 1(0,0) 2(0.5,0) 3(1,0) 4(1.5,0) 5(2,0) 6(2.5,0) 7(3,0) 8(3.5,0) 9(4,0) 10(4.5,0) 11(5,0) 12(5.5,0) 13(6,0) 14(6.5,0) 15(7,0) 16(7.5,0)
  rect 0.991x2.007 smd: 17(-2.1,-3.05) 18(9.6,-3.05)
AO4728L_SO8
  oval 0.635x1.854 smd: 1(0,0) 2(1.27,0) 3(2.54,0) 4(3.81,0) 5(3.81,5.165) 6(2.54,5.165) 7(1.27,5.165) 8(0,5.165)
AP2330W-7_SC59-3
  oval 0.787x0.991 smd: 1(0,0) 2(-0.95,-2.4) 3(0.95,-2.4)
AT97SC3204-X2A14-AB_TSSOP28
  oval 0.381x1.626 smd: 1(0,0) 2(0.65,0) 3(1.3,0) 4(1.95,0) 5(2.6,0) 6(3.25,0) 7(3.9,0) 8(4.55,0) 9(5.2,0) 10(5.85,0) 11(6.5,0) 12(7.15,0) 13(7.8,0) 14(8.45,0) 15(8.45,5.8) 16(7.8,5.8) 17(7.15,5.8) 18(6.5,5.8) 19(5.85,5.8) 20(5.2,5.8) 21(4.55,5.8) 22(3.9,5.8) 23(3.25,5.8) 24(2.6,5.8) 25(1.95,5.8) 26(1.3,5.8) 27(0.65,5.8) 28(0,5.8)
AZ5125-02SPR7G_SOT23-3
  oval 1.016x1.524 smd: 1(0,0) 2(0.965,2.083) 3(-0.965,2.083)
BAS40CW_SOT323-3
  oval 0.813x0.914 smd: 1(0,0) 2(0.65,1.6) 3(-0.65,1.6)
BAT54CW_SOT323-3
  oval 0.66x0.864 smd: 1(0,0) 2(-0.65,-1.85) 3(0.65,-1.85)
BD82PPSM-QNHN-A0_BGA_989P
  round 0.33 smd: A4(-1.431,0) A5(-2.031,0) A6(-2.631,0) A44(-20.996,0) A45(-21.596,0) A46(-22.196,0) B3(-0.914,0.517) B47(-22.713,0.517) BD1(0,20.996) BD49(-23.627,20.996) BE1(0,21.596) BE49(-23.627,21.596) BF1(0,22.196) BF49(-23.627,22.196) BG2(-0.457,22.653) BG48(-23.17,22.653) BH3(-0.914,23.11) BH47(-22.713,23.11) BJ4(-1.431,23.627) BJ5(-2.031,23.627) BJ6(-2.631,23.627) BJ44(-20.996,23.627) BJ45(-21.596,23.627) BJ46(-22.196,23.627) C2(-0.457,0.974) C48(-23.17,0.974) D1(0,1.431) D49(-23.627,1.431) E1(0,2.031) E49(-23.627,2.031) F1(0,2.631) F49(-23.627,2.631)
  round 0.305 smd: A8(-3.393,0) A10(-4.384,0) A12(-5.375,0) A14(-6.365,0) A16(-7.356,0) A18(-8.346,0) A20(-9.337,0) A22(-10.328,0) A24(-11.318,0) A26(-12.309,0) A28(-13.299,0) A30(-14.29,0) A32(-15.281,0) A34(-16.271,0) A36(-17.262,0) A38(-18.252,0) A40(-19.243,0) A42(-20.234,0) AA2(-0.447,9.832) AA3(-1.234,9.832) AA16(-7.394,9.832) AA17(-8.156,9.832) AA19(-8.969,9.832) AA21(-9.782,9.832) AA23(-10.594,9.832) AA24(-11.407,9.832) AA26(-12.22,9.832) AA27(-13.033,9.832) AA29(-13.846,9.832) AA31(-14.658,9.832) AA33(-15.471,9.832) AA34(-16.233,9.832) AA47(-22.393,9.832) AA48(-23.18,9.832) AB1(0,10.328) AB3(-0.892,10.328) AB4(-1.577,10.328) AB5(-2.212,10.328) AB7(-2.847,10.328) AB8(-3.482,10.328) AB10(-4.117,10.328) AB11(-4.752,10.328) AB12(-5.413,10.328) AB13(-6.099,10.328) AB14(-6.784,10.328) AB36(-16.843,10.328) AB37(-17.529,10.328) AB38(-18.214,10.328) AB39(-18.875,10.328) AB40(-19.51,10.328) AB42(-20.145,10.328) AB43(-20.78,10.328) AB45(-21.415,10.328) AB46(-22.05,10.328) AB47(-22.736,10.328) AB49(-23.627,10.328) AC2(-0.447,10.823) AC16(-7.394,10.645) AC17(-8.156,10.645) AC19(-8.969,10.645) AC21(-9.782,10.645) AC23(-10.594,10.645) AC24(-11.407,10.645) AC26(-12.22,10.645) AC27(-13.033,10.645) AC29(-13.846,10.645) AC31(-14.658,10.645) AC33(-15.471,10.645) AC34(-16.233,10.645) AC48(-23.18,10.823) AD1(0,11.318) AD3(-0.892,11.318) AD4(-1.577,11.318) AD5(-2.212,11.318) AD7(-2.847,11.318) AD8(-3.482,11.318) AD10(-4.117,11.318) AD11(-4.752,11.318) AD12(-5.413,11.318) AD13(-6.099,11.318) AD14(-6.784,11.318) AD16(-7.394,11.458) AD17(-8.156,11.458) AD19(-8.969,11.458) AD21(-9.782,11.458) AD23(-10.594,11.458) AD24(-11.407,11.458) AD26(-12.22,11.458) AD27(-13.033,11.458) AD29(-13.846,11.458) AD31(-14.658,11.458) AD33(-15.471,11.458) AD34(-16.233,11.458) AD36(-16.843,11.318) AD37(-17.529,11.318) AD38(-18.214,11.318) AD39(-18.875,11.318) AD40(-19.51,11.318) AD42(-20.145,11.318) AD43(-20.78,11.318) AD45(-21.415,11.318) AD46(-22.05,11.318) AD47(-22.736,11.318) AD49(-23.627,11.318) AE2(-0.447,11.814) AE3(-1.234,11.814) AE47(-22.393,11.814) AE48(-23.18,11.814) AF1(0,12.309) AF3(-0.892,12.309) AF4(-1.577,12.309) AF5(-2.212,12.309) AF7(-2.847,12.309) AF8(-3.482,12.309) AF10(-4.117,12.309) AF11(-4.752,12.309) AF12(-5.413,12.309) AF13(-6.099,12.309) AF14(-6.784,12.309) AF16(-7.394,12.271) AF17(-8.156,12.271) AF19(-8.969,12.271) AF21(-9.782,12.271) AF23(-10.594,12.271) AF24(-11.407,12.271) AF26(-12.22,12.271) AF27(-13.033,12.271) AF29(-13.846,12.271) AF31(-14.658,12.271) AF33(-15.471,12.271) AF34(-16.208,12.271) AF36(-16.843,12.309) AF37(-17.529,12.309) AF38(-18.214,12.309) AF39(-18.875,12.309) AF40(-19.51,12.309) AF42(-20.145,12.309) AF43(-20.78,12.309) AF45(-21.415,12.309) AF46(-22.05,12.309) AF47(-22.736,12.309) AF49(-23.627,12.309) AG2(-0.447,12.804) AG16(-7.394,13.084) AG17(-8.156,13.084) AG19(-8.969,13.084) AG21(-9.782,13.084) AG23(-10.594,13.084) AG24(-11.407,13.084) AG26(-12.22,13.084) AG27(-13.033,13.084) AG29(-13.846,13.084) AG31(-14.658,13.084) AG33(-15.471,13.084) AG34(-16.233,13.084) AG48(-23.18,12.804) AH1(0,13.299) AH3(-0.892,13.299) AH4(-1.577,13.299) AH5(-2.212,13.299) AH7(-2.847,13.299) AH8(-3.482,13.299) AH10(-4.117,13.299) AH11(-4.752,13.299) AH12(-5.413,13.299) AH13(-6.099,13.299) AH14(-6.784,13.299) AH36(-16.843,13.299) AH37(-17.529,13.299) AH38(-18.214,13.299) AH39(-18.875,13.299) AH40(-19.51,13.299) AH42(-20.145,13.299) AH43(-20.78,13.299) AH45(-21.415,13.299) AH46(-22.05,13.299) AH47(-22.736,13.299) AH49(-23.627,13.299) AJ2(-0.447,13.795) AJ3(-1.234,13.795) AJ16(-7.394,13.896) AJ17(-8.156,13.896) AJ19(-8.969,13.896) AJ21(-9.782,13.896) AJ23(-10.594,13.896) AJ24(-11.407,13.896) AJ26(-12.22,13.896) AJ27(-13.033,13.896) AJ29(-13.846,13.896) AJ31(-14.658,13.896) AJ33(-15.471,13.896) AJ34(-16.233,13.896) AJ47(-22.393,13.795) AJ48(-23.18,13.795) AK1(0,14.29) AK3(-0.892,14.29) AK4(-1.577,14.29) AK5(-2.212,14.29) AK7(-2.847,14.29) AK8(-3.482,14.29) AK10(-4.117,14.29) AK11(-4.752,14.29) AK12(-5.413,14.29) AK13(-6.099,14.29) AK14(-6.784,14.29) AK36(-16.843,14.29) AK37(-17.529,14.29) AK38(-18.214,14.29) AK39(-18.875,14.29) AK40(-19.51,14.29) AK42(-20.145,14.29) AK43(-20.78,14.29) AK45(-21.415,14.29) AK46(-22.05,14.29) AK47(-22.736,14.29) AK49(-23.627,14.29) AL2(-0.447,14.785) AL16(-7.394,14.709) AL17(-8.156,14.709) AL19(-8.969,14.709) AL21(-9.782,14.709) AL23(-10.594,14.709) AL24(-11.407,14.709) AL26(-12.22,14.709) AL27(-13.033,14.709) AL29(-13.846,14.709) AL31(-14.658,14.709) AL33(-15.471,14.709) AL34(-16.233,14.709) AL48(-23.18,14.785) AM1(0,15.281) AM3(-0.892,15.281) AM4(-1.577,15.281) AM5(-2.212,15.281) AM7(-2.847,15.281) AM8(-3.482,15.281) AM10(-4.117,15.281) AM11(-4.752,15.281) AM12(-5.413,15.281) AM13(-6.099,15.281) AM14(-6.784,15.281) AM36(-16.843,15.281) AM37(-17.529,15.281) AM38(-18.214,15.281) AM39(-18.875,15.281) AM40(-19.51,15.281) AM42(-20.145,15.281) AM43(-20.78,15.281) AM45(-21.415,15.281) AM46(-22.05,15.281) AM47(-22.736,15.281) AM49(-23.627,15.281) AN2(-0.447,15.776) AN3(-1.234,15.776) AN16(-7.394,15.522) AN17(-8.156,15.522) AN19(-8.969,15.522) AN21(-9.782,15.522) AN23(-10.594,15.522) AN24(-11.407,15.522) AN26(-12.22,15.522) AN27(-13.033,15.522) AN29(-13.846,15.522) AN31(-14.658,15.522) AN33(-15.471,15.522) AN34(-16.233,15.522) AN47(-22.393,15.776) AN48(-23.18,15.776) AP1(0,16.271) AP3(-0.892,16.271) AP4(-1.577,16.271) AP5(-2.212,16.271) AP7(-2.847,16.271) AP8(-3.482,16.271) AP10(-4.117,16.271) AP11(-4.752,16.271) AP12(-5.413,16.271) AP13(-6.099,16.271) AP14(-6.784,16.271) AP16(-7.394,16.157) AP17(-8.346,16.157) AP19(-9.337,16.157) AP21(-10.328,16.157) AP23(-11.318,16.157) AP24(-12.309,16.157) AP26(-13.299,16.157) AP28(-14.29,16.157) AP30(-15.281,16.157) AP32(-16.233,16.157) AP36(-16.843,16.271) AP37(-17.529,16.271) AP38(-18.214,16.271) AP39(-18.875,16.271) AP40(-19.51,16.271) AP42(-20.145,16.271) AP43(-20.78,16.271) AP45(-21.415,16.271) AP46(-22.05,16.271) AP47(-22.736,16.271) AP49(-23.627,16.271) AR2(-0.447,16.767) AR48(-23.18,16.767) AT1(0,17.262) AT3(-0.892,17.262) AT4(-1.577,17.262) AT5(-2.212,17.262) AT7(-2.847,17.262) AT8(-3.482,17.262) AT10(-4.117,17.262) AT11(-4.752,17.262) AT12(-5.413,17.262) AT13(-6.099,17.262) AT16(-7.356,16.843) AT18(-8.346,16.843) AT20(-9.337,16.843) AT22(-10.328,16.843) AT24(-11.318,16.843) AT26(-12.309,16.843) AT28(-13.299,16.843) AT30(-14.29,16.843) AT32(-15.281,16.843) AT34(-16.271,16.843) AT38(-18.214,17.262) AT39(-18.875,17.262) AT40(-19.51,17.262) AT42(-20.145,17.262) AT43(-20.78,17.262) AT45(-21.415,17.262) AT46(-22.05,17.262) AT47(-22.736,17.262) AT49(-23.627,17.262) AU2(-0.447,17.757) AU3(-1.234,17.757) AU16(-7.356,17.529) AU18(-8.346,17.529) AU20(-9.337,17.529) AU22(-10.328,17.529) AU24(-11.318,17.529) AU26(-12.309,17.529) AU28(-13.299,17.529) AU30(-14.29,17.529) AU32(-15.281,17.529) AU34(-16.271,17.529) AU36(-17.262,17.529) AU47(-22.393,17.757) AU48(-23.18,17.757) AV1(0,18.252) AV3(-0.892,18.252) AV4(-1.577,18.252) AV5(-2.212,18.252) AV7(-2.847,18.252) AV8(-3.482,18.252) AV10(-4.117,18.252) AV11(-4.752,18.252) AV12(-5.413,18.252) AV14(-6.365,18.214) AV16(-7.356,18.214) AV18(-8.346,18.214) AV20(-9.337,18.214) AV22(-10.328,18.214) AV24(-11.318,18.214) AV26(-12.309,18.214) AV28(-13.299,18.214) AV30(-14.29,18.214) AV32(-15.281,18.214) AV34(-16.271,18.214) AV36(-17.262,18.214) AV38(-18.252,18.214) AV40(-19.51,18.252) AV42(-20.145,18.252) AV43(-20.78,18.252) AV45(-21.415,18.252) AV46(-22.05,18.252) AV47(-22.736,18.252) AV49(-23.627,18.252) AW2(-0.447,18.748) AW14(-6.365,18.875) AW16(-7.356,18.875) AW18(-8.346,18.875) AW20(-9.337,18.875) AW22(-10.328,18.875) AW24(-11.318,18.875) AW26(-12.309,18.875) AW28(-13.299,18.875) AW30(-14.29,18.875) AW32(-15.281,18.875) AW34(-16.271,18.875) AW36(-17.262,18.875) AW38(-18.252,18.875) AW40(-19.243,18.875) AW48(-23.18,18.748) AY1(0,19.243) AY3(-0.892,19.243) AY4(-1.577,19.243) AY5(-2.212,19.243) AY7(-2.847,19.243) AY8(-3.482,19.243) AY10(-4.117,19.243) AY11(-4.752,19.243) AY12(-5.375,19.51) AY14(-6.365,19.51) AY16(-7.356,19.51) AY18(-8.346,19.51) AY20(-9.337,19.51) AY22(-10.328,19.51) AY24(-11.318,19.51) AY26(-12.309,19.51) AY28(-13.299,19.51) AY30(-14.29,19.51) AY32(-15.281,19.51) AY34(-16.271,19.51) AY36(-17.262,19.51) AY38(-18.252,19.51) AY40(-19.243,19.51) AY42(-20.145,19.243) AY43(-20.78,19.243) AY45(-21.415,19.243) AY46(-22.05,19.243) AY47(-22.736,19.243) AY49(-23.627,19.243) B7(-2.898,0.538) B9(-3.889,0.447) B11(-4.879,0.447) B13(-5.87,0.447) B15(-6.861,0.447) B17(-7.851,0.447) B19(-8.842,0.447) B21(-9.832,0.447) B23(-10.823,0.447) B25(-11.814,0.447) B27(-12.804,0.447) B29(-13.795,0.447) B31(-14.785,0.447) B33(-15.776,0.447) B35(-16.767,0.447) B37(-17.757,0.447) B39(-18.748,0.447) B41(-19.738,0.447) B43(-20.729,0.538) BA2(-0.447,19.738) BA3(-1.234,19.738) BA47(-22.393,19.738) BA48(-23.18,19.738) BB1(0,20.234) BB3(-0.892,20.234) BB4(-1.577,20.234) BB5(-2.212,20.234) BB7(-2.847,20.234) BB10(-4.384,20.145) BB12(-5.375,20.145) BB14(-6.365,20.145) BB16(-7.356,20.145) BB18(-8.346,20.145) BB20(-9.337,20.145) BB22(-10.328,20.145) BB24(-11.318,20.145) BB26(-12.309,20.145) BB28(-13.299,20.145) BB30(-14.29,20.145) BB32(-15.281,20.145) BB34(-16.271,20.145) BB36(-17.262,20.145) BB38(-18.252,20.145) BB40(-19.243,20.145) BB43(-20.78,20.234) BB45(-21.415,20.234) BB46(-22.05,20.234) BB47(-22.736,20.234) BB49(-23.627,20.234) BC2(-0.538,20.729) BC8(-3.393,20.78) BC10(-4.384,20.78) BC12(-5.375,20.78) BC14(-6.365,20.78) BC16(-7.356,20.78) BC18(-8.346,20.78) BC20(-9.337,20.78) BC22(-10.328,20.78) BC24(-11.318,20.78) BC26(-12.309,20.78) BC28(-13.299,20.78) BC30(-14.29,20.78) BC32(-15.281,20.78) BC34(-16.271,20.78) BC36(-17.262,20.78) BC38(-18.252,20.78) BC40(-19.243,20.78) BC42(-20.234,20.78) BC48(-23.089,20.729) BD3(-0.892,21.224) BD4(-1.577,21.224) BD5(-2.212,21.224) BD46(-22.05,21.224) BD47(-22.736,21.224) BE8(-3.393,21.415) BE10(-4.384,21.415) BE12(-5.375,21.415) BE14(-6.365,21.415) BE16(-7.356,21.415) BE18(-8.346,21.415) BE20(-9.337,21.415) BE22(-10.328,21.415) BE24(-11.318,21.415) BE26(-12.309,21.415) BE28(-13.299,21.415) BE30(-14.29,21.415) BE32(-15.281,21.415) BE34(-16.271,21.415) BE36(-17.262,21.415) BE38(-18.252,21.415) BE40(-19.243,21.415) BE42(-20.234,21.415) BE44(-21.224,21.415) BF3(-0.892,22.215) BF6(-2.403,22.05) BF8(-3.393,22.05) BF10(-4.384,22.05) BF12(-5.375,22.05) BF14(-6.365,22.05) BF16(-7.356,22.05) BF18(-8.346,22.05) BF20(-9.337,22.05) BF22(-10.328,22.05) BF24(-11.318,22.05) BF26(-12.309,22.05) BF28(-13.299,22.05) BF30(-14.29,22.05) BF32(-15.281,22.05) BF34(-16.271,22.05) BF36(-17.262,22.05) BF38(-18.252,22.05) BF40(-19.243,22.05) BF42(-20.234,22.05) BF44(-21.224,22.05) BF47(-22.736,22.215) BG4(-1.412,22.736) BG6(-2.403,22.736) BG8(-3.393,22.736) BG9(-3.889,22.393) BG10(-4.384,22.736) BG12(-5.375,22.736) BG13(-5.87,22.393) BG14(-6.365,22.736) BG16(-7.356,22.736) BG17(-7.851,22.393) BG18(-8.346,22.736) BG20(-9.337,22.736) BG21(-9.832,22.393) BG22(-10.328,22.736) BG24(-11.318,22.736) BG25(-11.814,22.393) BG26(-12.309,22.736) BG28(-13.299,22.736) BG29(-13.795,22.393) BG30(-14.29,22.736) BG32(-15.281,22.736) BG33(-15.776,22.393) BG34(-16.271,22.736) BG36(-17.262,22.736) BG37(-17.757,22.393) BG38(-18.252,22.736) BG40(-19.243,22.736) BG41(-19.738,22.393) BG42(-20.234,22.736) BG44(-21.224,22.736) BG46(-22.215,22.736) BH7(-2.898,23.089) BH9(-3.889,23.18) BH11(-4.879,23.18) BH13(-5.87,23.18) BH15(-6.861,23.18) BH17(-7.851,23.18) BH19(-8.842,23.18) BH21(-9.832,23.18) BH23(-10.823,23.18) BH25(-11.814,23.18) BH27(-12.804,23.18) BH29(-13.795,23.18) BH31(-14.785,23.18) BH33(-15.776,23.18) BH35(-16.767,23.18) BH37(-17.757,23.18) BH39(-18.748,23.18) BH41(-19.738,23.18) BH43(-20.729,23.089) BJ8(-3.393,23.627) BJ10(-4.384,23.627) BJ12(-5.375,23.627) BJ14(-6.365,23.627) BJ16(-7.356,23.627) BJ18(-8.346,23.627) BJ20(-9.337,23.627) BJ22(-10.328,23.627) BJ24(-11.318,23.627) BJ26(-12.309,23.627) BJ28(-13.299,23.627) BJ30(-14.29,23.627) BJ32(-15.281,23.627) BJ34(-16.271,23.627) BJ36(-17.262,23.627) BJ38(-18.252,23.627) BJ40(-19.243,23.627) BJ42(-20.234,23.627) C4(-1.412,0.892) C6(-2.403,0.892) C8(-3.393,0.892) C9(-3.889,1.234) C10(-4.384,0.892) C12(-5.375,0.892) C13(-5.87,1.234) C14(-6.365,0.892) C16(-7.356,0.892) C17(-7.851,1.234) C18(-8.346,0.892) C20(-9.337,0.892) C21(-9.832,1.234) C22(-10.328,0.892) C24(-11.318,0.892) C25(-11.814,1.234) C26(-12.309,0.892) C28(-13.299,0.892) C29(-13.795,1.234) C30(-14.29,0.892) C32(-15.281,0.892) C33(-15.776,1.234) C34(-16.271,0.892) C36(-17.262,0.892) C37(-17.757,1.234) C38(-18.252,0.892) C40(-19.243,0.892) C41(-19.738,1.234) C42(-20.234,0.892) C44(-21.224,0.892) C46(-22.215,0.892) D3(-0.892,1.412) D6(-2.403,1.577) D8(-3.393,1.577) D10(-4.384,1.577) D12(-5.375,1.577) D14(-6.365,1.577) D16(-7.356,1.577) D18(-8.346,1.577) D20(-9.337,1.577) D22(-10.328,1.577) D24(-11.318,1.577) D26(-12.309,1.577) D28(-13.299,1.577) D30(-14.29,1.577) D32(-15.281,1.577) D34(-16.271,1.577) D36(-17.262,1.577) D38(-18.252,1.577) D40(-19.243,1.577) D42(-20.234,1.577) D44(-21.224,1.577) D47(-22.736,1.412) E6(-2.403,2.212) E8(-3.393,2.212) E10(-4.384,2.212) E12(-5.375,2.212) E14(-6.365,2.212) E16(-7.356,2.212) E18(-8.346,2.212) E20(-9.337,2.212) E22(-10.328,2.212) E24(-11.318,2.212) E26(-12.309,2.212) E28(-13.299,2.212) E30(-14.29,2.212) E32(-15.281,2.212) E34(-16.271,2.212) E36(-17.262,2.212) E38(-18.252,2.212) E40(-19.243,2.212) E42(-20.234,2.212) F3(-0.892,2.403) F4(-1.577,2.403) F45(-21.415,2.403) F46(-22.05,2.403) F47(-22.736,2.403) G2(-0.538,2.898) G8(-3.393,2.847) G10(-4.384,2.847) G12(-5.375,2.847) G14(-6.365,2.847) G16(-7.356,2.847) G18(-8.346,2.847) G20(-9.337,2.847) G22(-10.328,2.847) G24(-11.318,2.847) G26(-12.309,2.847) G28(-13.299,2.847) G30(-14.29,2.847) G32(-15.281,2.847) G34(-16.271,2.847) G36(-17.262,2.847) G38(-18.252,2.847) G40(-19.243,2.847) G42(-20.234,2.847) G48(-23.089,2.898) H1(0,3.393) H3(-0.892,3.393) H4(-1.577,3.393) H5(-2.212,3.393) H7(-2.847,3.393) H10(-4.384,3.482) H12(-5.375,3.482) H14(-6.365,3.482) H16(-7.356,3.482) H18(-8.346,3.482) H20(-9.337,3.482) H22(-10.328,3.482) H24(-11.318,3.482) H26(-12.309,3.482) H28(-13.299,3.482) H30(-14.29,3.482) H32(-15.281,3.482) H34(-16.271,3.482) H36(-17.262,3.482) H38(-18.252,3.482) H40(-19.243,3.482) H43(-20.78,3.393) H45(-21.415,3.393) H46(-22.05,3.393) H47(-22.736,3.393) H49(-23.627,3.393) J2(-0.447,3.889) J3(-1.234,3.889) J47(-22.393,3.889) J48(-23.18,3.889) K1(0,4.384) K3(-0.892,4.384) K4(-1.577,4.384) K5(-2.212,4.384) K7(-2.847,4.384) K10(-4.384,4.117) K12(-5.375,4.117) K14(-6.365,4.117) K16(-7.356,4.117) K18(-8.346,4.117) K20(-9.337,4.117) K22(-10.328,4.117) K24(-11.318,4.117) K26(-12.309,4.117) K28(-13.299,4.117) K30(-14.29,4.117) K32(-15.281,4.117) K34(-16.271,4.117) K36(-17.262,4.117) K38(-18.252,4.117) K39(-18.875,4.384) K40(-19.51,4.384) K42(-20.145,4.384) K43(-20.78,4.384) K45(-21.415,4.384) K46(-22.05,4.384) K47(-22.736,4.384) K49(-23.627,4.384) L2(-0.447,4.879) L10(-4.384,4.752) L12(-5.375,4.752) L14(-6.365,4.752) L16(-7.356,4.752) L18(-8.346,4.752) L20(-9.337,4.752) L22(-10.328,4.752) L24(-11.318,4.752) L26(-12.309,4.752) L28(-13.299,4.752) L30(-14.29,4.752) L32(-15.281,4.752) L34(-16.271,4.752) L36(-17.262,4.752) L48(-23.18,4.879) M1(0,5.375) M3(-0.892,5.375) M4(-1.577,5.375) M5(-2.212,5.375) M7(-2.847,5.375) M8(-3.482,5.375) M10(-4.117,5.375) M12(-5.375,5.362) M14(-6.365,5.464) M16(-7.356,5.464) M18(-8.346,5.413) M20(-9.337,5.413) M22(-10.328,5.413) M24(-11.318,5.413) M26(-12.309,5.413) M28(-13.299,5.413) M30(-14.29,5.413) M32(-15.281,5.413) M34(-16.271,5.413) M36(-17.262,5.464) M38(-18.214,5.375) M39(-18.875,5.375) M40(-19.51,5.375) M42(-20.145,5.375) M43(-20.78,5.375) M45(-21.415,5.375) M46(-22.05,5.375) M47(-22.736,5.375) M49(-23.627,5.375) N2(-0.447,5.87) N3(-1.234,5.87) N14(-6.365,6.099) N16(-7.356,6.099) N18(-8.346,6.099) N20(-9.337,6.099) N22(-10.328,6.099) N24(-11.318,6.099) N26(-12.309,6.099) N28(-13.299,6.099) N30(-14.29,6.099) N32(-15.281,6.099) N34(-16.271,6.099) N47(-22.393,5.87) N48(-23.18,5.87) P1(0,6.365) P3(-0.892,6.365) P4(-1.577,6.365) P5(-2.212,6.365) P7(-2.847,6.365) P8(-3.482,6.365) P10(-4.117,6.365) P11(-4.752,6.365) P12(-5.438,6.365) P16(-7.356,6.784) P18(-8.346,6.784) P20(-9.337,6.784) P22(-10.328,6.784) P24(-11.318,6.784) P26(-12.309,6.784) P28(-13.299,6.784) P30(-14.29,6.784) P32(-15.281,6.784) P34(-16.271,6.784) P37(-17.529,6.365) P38(-18.214,6.365) P39(-18.875,6.365) P40(-19.51,6.365) P42(-20.145,6.365) P43(-20.78,6.365) P45(-21.415,6.365) P46(-22.05,6.365) P47(-22.736,6.365) P49(-23.627,6.365) R2(-0.447,6.861) R48(-23.18,6.861) T1(0,7.356) T3(-0.892,7.356) T4(-1.577,7.356) T5(-2.212,7.356) T7(-2.847,7.356) T8(-3.482,7.356) T10(-4.117,7.356) T11(-4.752,7.356) T12(-5.413,7.356) T13(-6.099,7.356) T14(-6.759,7.356) T16(-7.394,7.394) T17(-8.156,7.394) T19(-8.969,7.394) T21(-9.782,7.394) T23(-10.594,7.394) T24(-11.407,7.394) T26(-12.22,7.394) T27(-13.033,7.394) T29(-13.846,7.394) T31(-14.658,7.394) T33(-15.471,7.394) T34(-16.233,7.394) T36(-16.843,7.356) T37(-17.529,7.356) T38(-18.214,7.356) T39(-18.875,7.356) T40(-19.51,7.356) T42(-20.145,7.356) T43(-20.78,7.356) T45(-21.415,7.356) T46(-22.05,7.356) T47(-22.736,7.356) T49(-23.627,7.356) U2(-0.447,7.851) U3(-1.234,7.851) U47(-22.393,7.851) U48(-23.18,7.851) V1(0,8.346) V3(-0.892,8.346) V4(-1.577,8.346) V5(-2.212,8.346) V7(-2.847,8.346) V8(-3.482,8.346) V10(-4.117,8.346) V11(-4.752,8.346) V12(-5.413,8.346) V13(-6.099,8.346) V14(-6.784,8.346) V16(-7.394,8.207) V17(-8.156,8.207) V19(-8.969,8.207) V21(-9.782,8.207) V23(-10.594,8.207) V24(-11.407,8.207) V26(-12.22,8.207) V27(-13.033,8.207) V29(-13.846,8.207) V31(-14.658,8.207) V33(-15.471,8.207) V34(-16.233,8.207) V36(-16.843,8.346) V37(-17.529,8.346) V38(-18.214,8.346) V39(-18.875,8.346) V40(-19.51,8.346) V42(-20.145,8.346) V43(-20.78,8.346) V45(-21.415,8.346) V46(-22.05,8.346) V47(-22.736,8.346) V49(-23.627,8.346) W2(-0.447,8.842) W16(-7.394,9.02) W17(-8.156,9.02) W19(-8.969,9.02) W21(-9.782,9.02) W23(-10.594,9.02) W24(-11.407,9.02) W26(-12.22,9.02) W27(-13.033,9.02) W29(-13.846,9.02) W31(-14.658,9.02) W33(-15.471,9.02) W34(-16.233,9.02) W48(-23.18,8.842) Y1(0,9.337) Y3(-0.892,9.337) Y4(-1.577,9.337) Y5(-2.212,9.337) Y7(-2.847,9.337) Y8(-3.482,9.337) Y10(-4.117,9.337) Y11(-4.752,9.337) Y12(-5.413,9.337) Y13(-6.099,9.337) Y14(-6.784,9.337) Y36(-16.843,9.337) Y37(-17.529,9.337) Y38(-18.214,9.337) Y39(-18.875,9.337) Y40(-19.51,9.337) Y42(-20.145,9.337) Y43(-20.78,9.337) Y45(-21.415,9.337) Y46(-22.05,9.337) Y47(-22.736,9.337) Y49(-23.627,9.337)
BQ24745RHDR_QFN28_5X5
  oval 0.254x1.194 smd: 1(0,0) 2(0.5,0) 3(1,0) 4(1.5,0) 5(2.001,0) 6(2.501,0) 7(3.001,0) 15(3.001,4.8) 16(2.501,4.8) 17(2.001,4.8) 18(1.5,4.8) 19(1,4.8) 20(0.5,4.8) 21(0,4.8)
  oval 1.194x0.254 smd: 8(3.9,0.9) 9(3.9,1.4) 10(3.9,1.9) 11(3.9,2.4) 12(3.9,2.9) 13(3.9,3.4) 14(3.9,3.9) 22(-0.9,3.9) 23(-0.9,3.4) 24(-0.9,2.9) 25(-0.9,2.4) 26(-0.9,1.9) 27(-0.9,1.4) 28(-0.9,0.9)
  rect 2.692x2.692 smd: 29(1.5,2.4)
BSS138-G_SOT23-3
  oval 1.016x1.524 smd: 1(0,0) 2(0.965,2.083) 3(-0.965,2.083)
BSS138W-7-F_SOT323-3
  oval 0.711x0.889 smd: 1(0,0) 2(-0.65,-1.9) 3(0.65,-1.9)
C_0402NEW
  rect 0.508x0.559 smd: 1(0,0) 2(0.914,0)
C_0603NEW
  rect 0.635x0.889 smd: 1(0,0) 2(1.397,0)
C_0805NEW
  rect 0.813x1.397 smd: 1(0,0) 2(1.702,0)
C_1808
  rect 1.041x2.311 smd: 1(0,0) 2(4.35,0)
C_B2
  rect 1.346x2.692 smd: 1(0,0) 2(-2.75,0)
C_D
  rect 2.388x2.896 smd: 1(0,0) 2(6.1,0)
C_D2
  rect 2.388x2.794 smd: 1(0,0) 2(6.4,0)
C_D2E
  rect 2.388x2.896 smd: 1(0,0) 2(6.1,0)
C_D3
  rect 2.388x2.794 smd: 1(0,0) 2(6.4,0)
C_SX
  rect 2.388x2.794 smd: 1(0,0) 2(6,0)
CYNTE_PDME064T-R36MS1R405_4P
  custom 0.686x0.686 smd: 1(0,0) 4(8.509,0)
  rect 2.362x0.508 smd: 2(1.448,0) 3(7.061,0)
DELTA_0402HS-9N0EJTS_2P
  rect 0.508x0.66 smd: 1(0,0) 2(0.96,0)
DELTA_0603CS-120EJTS_2P
  rect 0.635x1.016 smd: 1(0,0) 2(1.28,0)
DMN66D0LDW-7_SOT363-6
  oval 0.432x0.61 smd: 1(0,0) 2(0.65,0) 3(1.3,0) 4(1.3,1.9) 5(0.65,1.9) 6(0,1.9)
DMN3030LSS-13_SOP8L-8
  oval 0.635x1.829 smd: 1(0,0) 2(1.27,0) 3(2.54,0) 4(3.81,0) 5(3.81,5.17) 6(2.54,5.17) 7(1.27,5.17) 8(0,5.17)
DTC115EUA_SC70-3
  oval 0.813x0.914 smd: 1(0,0) 2(0.65,1.6) 3(-0.65,1.6)
E-T_3703K-F12N-03R_12P
  oval 0.61x1.549 smd: 1(0,0) 2(1,0) 3(2,0) 4(3,0) 5(4,0) 6(5,0) 7(6,0) 8(7,0) 9(8,0) 10(9,0) 11(10,0) 12(11,0)
  rect 1.194x2.007 smd: 13(-1.3,-3.775) 14(12.3,-3.775)
ECE5048-LZY_DQFN132_11X11
  oval 0.279x0.737 smd: A1(0,0) A2(0.5,0) A3(1,0) A4(1.5,0) A5(2,0) A6(2.5,0) A7(3,0) A8(3.5,0) A9(4,0) A10(4.5,0) A11(5,0) A12(5.5,0) A13(6,0) A14(6.5,0) A15(7,0) A16(7.5,0) A33(7.5,10.9) A34(7,10.9) A35(6.5,10.9) A36(6,10.9) A37(5.5,10.9) A38(5,10.9) A39(4.5,10.9) A40(4,10.9) A41(3.5,10.9) A42(3,10.9) A43(2.5,10.9) A44(2,10.9) A45(1.5,10.9) A46(1,10.9) A47(0.5,10.9) A48(0,10.9)
  oval 0.737x0.279 smd: A17(9.2,1.7) A18(9.2,2.2) A19(9.2,2.7) A20(9.2,3.2) A21(9.2,3.7) A22(9.2,4.2) A23(9.2,4.7) A24(9.2,5.2) A25(9.2,5.7) A26(9.2,6.2) A27(9.2,6.7) A28(9.2,7.2) A29(9.2,7.7) A30(9.2,8.2) A31(9.2,8.7) A32(9.2,9.2) A49(-1.7,9.2) A50(-1.7,8.7) A51(-1.7,8.2) A52(-1.7,7.7) A53(-1.7,7.2) A54(-1.7,6.7) A55(-1.7,6.2) A56(-1.7,5.7) A57(-1.7,5.2) A58(-1.7,4.7) A59(-1.7,4.2) A60(-1.7,3.7) A61(-1.7,3.2) A62(-1.7,2.7) A63(-1.7,2.2) A64(-1.7,1.7)
  oval 0.318x0.61 smd: B1(-0.25,0.855) B2(0.25,0.855) B3(0.75,0.855) B4(1.25,0.855) B5(1.75,0.855) B6(2.25,0.855) B7(2.75,0.855) B8(3.25,0.855) B9(3.75,0.855) B10(4.25,0.855) B11(4.75,0.855) B12(5.25,0.855) B13(5.75,0.855) B14(6.25,0.855) B15(6.75,0.855) B16(7.25,0.855) B17(7.75,0.855) B35(7.75,10.045) B36(7.25,10.045) B37(6.75,10.045) B38(6.25,10.045) B39(5.75,10.045) B40(5.25,10.045) B41(4.75,10.045) B42(4.25,10.045) B43(3.75,10.045) B44(3.25,10.045) B45(2.75,10.045) B46(2.25,10.045) B47(1.75,10.045) B48(1.25,10.045) B49(0.75,10.045) B50(0.25,10.045) B51(-0.25,10.045)
  oval 0.61x0.318 smd: B18(8.345,1.45) B19(8.345,1.95) B20(8.345,2.45) B21(8.345,2.95) B22(8.345,3.45) B23(8.345,3.95) B24(8.345,4.45) B25(8.345,4.95) B26(8.345,5.45) B27(8.345,5.95) B28(8.345,6.45) B29(8.345,6.95) B30(8.345,7.45) B31(8.345,7.95) B32(8.345,8.45) B33(8.345,8.95) B34(8.345,9.45) B52(-0.845,9.45) B53(-0.845,8.95) B54(-0.845,8.45) B55(-0.845,7.95) B56(-0.845,7.45) B57(-0.845,6.95) B58(-0.845,6.45) B59(-0.845,5.95) B60(-0.845,5.45) B61(-0.845,4.95) B62(-0.845,4.45) B63(-0.845,3.95) B64(-0.845,3.45) B65(-0.845,2.95) B66(-0.845,2.45) B67(-0.845,1.95) B68(-0.845,1.45)
  rect 5.105x5.105 smd: C1(3.75,5.45)
